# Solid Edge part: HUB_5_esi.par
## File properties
Author: Türk
Template: Iso Part.par
Last saved by: Türk
Revision: 13
Application: Solid Edge
Accuracy: 0,990
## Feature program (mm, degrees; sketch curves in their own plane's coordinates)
thread "unnamed Thread 1"
pattern "unnamed Pattern 1" of "unnamed Thread 1"
pattern "PatternOccurrence_2"  XOffset = 72 deg
thread "unnamed Thread 2"
thread "unnamed Thread 3"
thread "unnamed Thread 4"
thread "unnamed Thread 5"
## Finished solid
Body 1: solid body, 33 faces, 51 edges, 20 vertices.
  Faces by surface: cylinder 23, plane 10
  Edges by curve: circle 41, line 10
Bounding box of the edges (mm): 110.451 x 177.000 x 115.106, from (-60, -102, -57.5528) to (50.4508, 75, 57.5528).
Cylindrical faces by radius (mm): R6 x10, R10 x5, R22 x1, R32.5 x2, R50 x5
Planar faces by outward normal: +y 7, -y 3
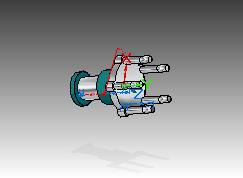
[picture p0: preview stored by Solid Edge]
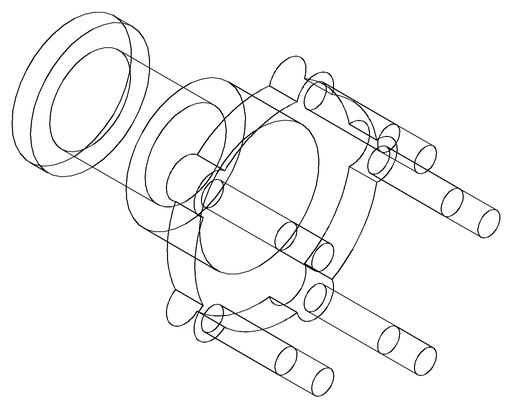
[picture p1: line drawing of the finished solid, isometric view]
